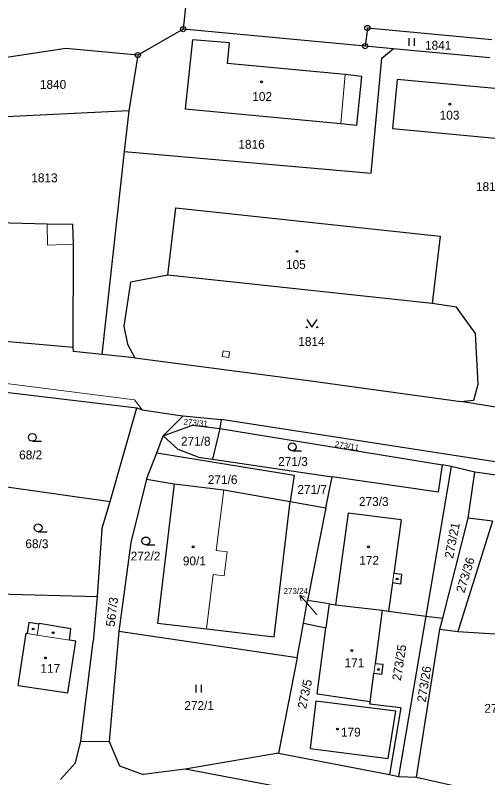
# Model space of a CAD drawing. Extents: x -601131 to -597152, y -1058536 to -1055911.
# Drawn here: x -599381.2 to -599290.5, y -1057201.3 to -1057055.1 of the extents above; entities that cross this region are included whole.
import ezdxf
from ezdxf.enums import TextEntityAlignment as Align

# ---------------------------------------------------------------- set-up
doc = ezdxf.new("R2010")
doc.units = 0
doc.header["$LTSCALE"] = 0.68
for name, color, linetype, lineweight in [('1', 7, 'Continuous', 25), ('3', 7, 'Continuous', 25), ('4', 7, 'Continuous', 13), ('5', 7, 'Continuous', 25), ('7', 7, 'Continuous', 13), ('8', 7, 'Continuous', 25)]:
    doc.layers.add(name, color=color, linetype=linetype, lineweight=lineweight)
doc.layers.add('2', color=7, linetype='Continuous')

msp = doc.modelspace()

# ---------------------------------------------------------------- linework, layer by layer
at = {"layer": '1'}
for p, q in [((-599345.57, -1057026.31), (-599349.02, -1057057.72)), ((-599349.02, -1057057.72), (-599357.72, -1057062.7)), ((-599314.09, -1057060.98), (-599349.02, -1057057.72)), ((-599313.65, -1057057.51), (-599314.09, -1057060.98)), ((-599289.75, -1057059.74), (-599313.65, -1057057.51)), ((-599347.24, -1057059.74), (-599348.63, -1057073.02)), ((-599340.09, -1057060.34), (-599347.24, -1057059.74)), ((-599340.49, -1057064.3), (-599340.09, -1057060.34)), ((-599308.72, -1057061.49), (-599314.09, -1057060.98)), ((-599371.54, -1057061.4), (-599383.28, -1057063.21)), ((-599357.72, -1057062.7), (-599371.54, -1057061.4)), ((-599310.9, -1057063.29), (-599308.72, -1057061.49)), ((-599290.14, -1057063.22), (-599308.72, -1057061.49)), ((-599357.72, -1057062.7), (-599359.44, -1057073.38)), ((-599312.94, -1057085.36), (-599310.9, -1057063.29)), ((-599317.89, -1057066.41), (-599340.49, -1057064.3)), ((-599314.7, -1057066.78), (-599317.89, -1057066.41)), ((-599315.69, -1057076.12), (-599314.7, -1057066.78)), ((-599307.96, -1057067.36), (-599308.83, -1057076.76)), ((-599285.62, -1057069.45), (-599307.96, -1057067.36)), ((-599359.44, -1057073.38), (-599384.42, -1057074.6)), ((-599359.44, -1057073.38), (-599360.32, -1057081.18)), ((-599348.63, -1057073.02), (-599318.77, -1057075.79)), ((-599318.77, -1057075.79), (-599315.69, -1057076.12)), ((-599308.83, -1057076.76), (-599286.54, -1057078.9)), ((-599360.32, -1057081.18), (-599364.64, -1057120.14)), ((-599360.32, -1057081.18), (-599312.94, -1057085.36)), ((-599351.94, -1057104.91), (-599350.44, -1057091.99)), ((-599350.44, -1057091.99), (-599299.69, -1057097.43)), ((-599375.11, -1057095.12), (-599389.23, -1057094.77)), ((-599370.16, -1057095.2), (-599375.11, -1057095.12)), ((-599370.08, -1057098.98), (-599370.16, -1057095.2)), ((-599299.69, -1057097.43), (-599301.18, -1057110.36)), ((-599370.11, -1057118.82), (-599370.08, -1057098.98)), ((-599351.94, -1057104.91), (-599359.13, -1057106.27)), ((-599301.18, -1057110.36), (-599351.94, -1057104.91)), ((-599359.13, -1057106.27), (-599360.39, -1057114.73)), ((-599296.51, -1057111.08), (-599301.18, -1057110.36)), ((-599292.92, -1057116.08), (-599296.51, -1057111.08)), ((-599360.39, -1057114.73), (-599359.72, -1057118.15)), ((-599292.39, -1057125.84), (-599292.92, -1057116.08)), ((-599370.11, -1057118.82), (-599392.44, -1057116.83)), ((-599359.72, -1057118.15), (-599358.28, -1057120.79)), ((-599370.06, -1057119.59), (-599370.11, -1057118.82)), ((-599364.64, -1057120.14), (-599370.06, -1057119.59)), ((-599358.28, -1057120.79), (-599364.64, -1057120.14)), ((-599358.28, -1057120.79), (-599324.53, -1057125.19)), ((-599324.53, -1057125.19), (-599295.71, -1057129.16)), ((-599392.5, -1057126.24), (-599357.9, -1057130.4)), ((-599293.18, -1057128.9), (-599292.39, -1057125.84)), ((-599295.71, -1057129.16), (-599293.18, -1057128.9)), ((-599293.72, -1057129.47), (-599295.71, -1057129.16)), ((-599283.88, -1057131.11), (-599293.72, -1057129.47)), ((-599363.04, -1057148.31), (-599357.9, -1057130.4)), ((-599357.9, -1057130.4), (-599356.88, -1057130.74)), ((-599356.88, -1057130.74), (-599350.04, -1057131.76)), ((-599352.87, -1057135.75), (-599348.99, -1057131.89)), ((-599350.04, -1057131.76), (-599348.99, -1057131.89)), ((-599348.99, -1057131.89), (-599341.7, -1057132.63)), ((-599341.7, -1057132.63), (-599341.95, -1057134.36)), ((-599279.34, -1057142.28), (-599341.7, -1057132.63)), ((-599352.87, -1057135.75), (-599347.22, -1057133.71)), ((-599347.22, -1057133.71), (-599341.95, -1057134.36)), ((-599354.07, -1057138.97), (-599352.87, -1057135.75)), ((-599352.87, -1057135.75), (-599349.95, -1057138.35)), ((-599341.95, -1057134.36), (-599343.35, -1057140.21)), ((-599341.95, -1057134.36), (-599299.2, -1057141.28)), ((-599346.16, -1057139.82), (-599349.95, -1057138.35)), ((-599356.03, -1057144.08), (-599354.07, -1057138.97)), ((-599354.07, -1057138.97), (-599327.73, -1057143.26)), ((-599346.16, -1057139.82), (-599343.35, -1057140.21)), ((-599343.35, -1057140.21), (-599320.42, -1057143.61)), ((-599299.97, -1057146.53), (-599299.2, -1057141.28)), ((-599297.54, -1057141.64), (-599299.2, -1057141.28)), ((-599297.54, -1057141.64), (-599302.44, -1057170.31)), ((-599293, -1057142.72), (-599297.54, -1057141.64)), ((-599294.32, -1057151.54), (-599293, -1057142.72)), ((-599279.71, -1057144.58), (-599293, -1057142.72)), ((-599394.87, -1057143.82), (-599363.04, -1057148.31)), ((-599356.03, -1057144.08), (-599359.06, -1057156.23)), ((-599356.03, -1057144.08), (-599350.75, -1057144.95)), ((-599327.73, -1057143.26), (-599328.49, -1057148.34)), ((-599321.65, -1057149.53), (-599320.42, -1057143.61)), ((-599299.97, -1057146.53), (-599320.42, -1057143.61)), ((-599350.75, -1057144.95), (-599353.95, -1057171.65)), ((-599350.75, -1057144.95), (-599341.22, -1057146.13)), ((-599341.22, -1057146.13), (-599328.49, -1057148.34)), ((-599364.62, -1057153.64), (-599363.04, -1057148.31)), ((-599331.57, -1057174.28), (-599328.49, -1057148.34)), ((-599328.49, -1057148.34), (-599321.65, -1057149.53)), ((-599321.65, -1057149.53), (-599325.14, -1057167.36)), ((-599317.36, -1057150.56), (-599319.79, -1057168.13)), ((-599307.19, -1057151.88), (-599317.36, -1057150.56)), ((-599299.15, -1057170.73), (-599294.32, -1057151.54)), ((-599289.64, -1057152.13), (-599294.32, -1057151.54)), ((-599307.19, -1057151.88), (-599308.59, -1057162.13)), ((-599289.64, -1057152.13), (-599296.29, -1057173.26)), ((-599364.62, -1057153.64), (-599365.52, -1057166.56)), ((-599359.06, -1057156.23), (-599361.33, -1057173.26)), ((-599307.08, -1057162.33), (-599308.59, -1057162.13)), ((-599307.08, -1057162.33), (-599307.32, -1057164.17)), ((-599308.84, -1057163.96), (-599309.58, -1057169.4)), ((-599307.32, -1057164.17), (-599308.84, -1057163.96)), ((-599395.07, -1057165.74), (-599365.52, -1057166.56)), ((-599365.52, -1057166.56), (-599366.32, -1057175.2)), ((-599325.93, -1057171.7), (-599325.14, -1057167.36)), ((-599320.98, -1057167.97), (-599325.14, -1057167.36)), ((-599320.98, -1057167.97), (-599321.6, -1057172.59)), ((-599320.98, -1057167.97), (-599319.79, -1057168.13)), ((-599319.79, -1057168.13), (-599310.82, -1057169.21)), ((-599310.82, -1057169.21), (-599312.17, -1057179.49)), ((-599310.82, -1057169.21), (-599309.58, -1057169.4)), ((-599309.58, -1057169.4), (-599302.44, -1057170.31)), ((-599302.44, -1057170.31), (-599307.7, -1057201.07)), ((-599302.44, -1057170.31), (-599299.15, -1057170.73)), ((-599299.74, -1057172.84), (-599299.15, -1057170.73)), ((-599378.65, -1057171.56), (-599378.97, -1057173.63)), ((-599376.7, -1057171.89), (-599378.65, -1057171.56)), ((-599376.68, -1057171.76), (-599376.7, -1057171.89)), ((-599370.58, -1057172.77), (-599376.68, -1057171.76)), ((-599353.95, -1057171.65), (-599344.52, -1057172.78)), ((-599327.12, -1057178.31), (-599325.93, -1057171.7)), ((-599325.93, -1057171.7), (-599324.38, -1057172.02)), ((-599324.38, -1057172.02), (-599321.89, -1057172.53)), ((-599380.68, -1057183.61), (-599379.12, -1057173.61)), ((-599379.12, -1057173.61), (-599378.97, -1057173.63)), ((-599370.86, -1057174.97), (-599370.58, -1057172.77)), ((-599361.33, -1057173.26), (-599363.21, -1057194.4)), ((-599327.12, -1057178.31), (-599361.33, -1057173.26)), ((-599344.52, -1057172.78), (-599331.57, -1057174.28)), ((-599323.31, -1057185.31), (-599321.6, -1057172.59)), ((-599321.89, -1057172.53), (-599321.6, -1057172.59)), ((-599304.24, -1057201.25), (-599299.74, -1057172.84)), ((-599299.74, -1057172.84), (-599296.29, -1057173.26)), ((-599296.29, -1057173.26), (-599274.91, -1057174.6)), ((-599371.18, -1057185.04), (-599369.62, -1057175.13)), ((-599369.62, -1057175.13), (-599370.86, -1057174.97)), ((-599368.68, -1057194.29), (-599366.32, -1057175.2)), ((-599327.12, -1057178.31), (-599330.73, -1057196.61)), ((-599310.63, -1057179.64), (-599312.17, -1057179.49)), ((-599310.88, -1057181.51), (-599310.63, -1057179.64)), ((-599313.12, -1057186.74), (-599312.41, -1057181.33)), ((-599310.88, -1057181.51), (-599312.41, -1057181.33)), ((-599380.68, -1057183.61), (-599371.18, -1057185.04)), ((-599313.12, -1057186.74), (-599323.31, -1057185.31)), ((-599323.53, -1057186.67), (-599324.62, -1057195.73)), ((-599308.18, -1057188.54), (-599323.53, -1057186.67)), ((-599313.12, -1057186.74), (-599313.26, -1057187.25)), ((-599307.23, -1057187.89), (-599313.26, -1057187.25)), ((-599307.23, -1057187.89), (-599309.37, -1057200.73)), ((-599309.65, -1057197.67), (-599308.18, -1057188.54)), ((-599369.66, -1057198.5), (-599368.68, -1057194.29)), ((-599368.68, -1057194.29), (-599363.21, -1057194.4)), ((-599363.21, -1057194.4), (-599361.26, -1057199.05)), ((-599324.62, -1057195.73), (-599309.65, -1057197.67)), ((-599330.73, -1057196.61), (-599348.62, -1057199.67)), ((-599330.73, -1057196.61), (-599309.37, -1057200.73)), ((-599372.53, -1057201.69), (-599369.66, -1057198.5)), ((-599361.26, -1057199.05), (-599356.7, -1057200.73)), ((-599348.62, -1057199.67), (-599356.7, -1057200.73)), ((-599331.73, -1057202.88), (-599348.62, -1057199.67)), ((-599309.37, -1057200.73), (-599307.7, -1057201.07)), ((-599307.7, -1057201.07), (-599304.24, -1057201.25)), ((-599304.24, -1057201.25), (-599280.22, -1057206.58))]:
    msp.add_line(p, q, dxfattribs=at)
at = {"layer": '3'}
for p, q in [((-599305.621, -1057060.92), (-599305.621, -1057059.42)), ((-599304.62, -1057060.92), (-599304.62, -1057059.42)), ((-599377.963, -1057136.79), (-599376.213, -1057136.79)), ((-599328.053, -1057138.61), (-599326.303, -1057138.61)), ((-599376.853, -1057154.15), (-599375.103, -1057154.15)), ((-599356.173, -1057156.65), (-599354.423, -1057156.65)), ((-599346.491, -1057184.99), (-599346.491, -1057183.49)), ((-599345.49, -1057184.99), (-599345.49, -1057183.49))]:
    msp.add_line(p, q, dxfattribs=at)
msp.add_lwpolyline([(-599325.28, -1057113.419), (-599324.28, -1057114.92), (-599323.28, -1057113.419)], dxfattribs=at)
for centre, radius in [((-599325.28, -1057114.9195), 0.1), ((-599323.28, -1057114.9195), 0.1), ((-599377.9629, -1057136.0398), 0.75), ((-599328.0529, -1057137.8598), 0.75), ((-599376.8529, -1057153.3998), 0.75), ((-599356.1729, -1057155.8998), 0.75)]:
    msp.add_circle(centre, radius, dxfattribs=at)
at = {"layer": '4'}
for p, q in [((-599317.89, -1057066.41), (-599318.77, -1057075.79)), ((-599375.06, -1057099.18), (-599375.11, -1057095.12)), ((-599375.06, -1057099.18), (-599370.08, -1057098.98)), ((-599341.51, -1057120.52), (-599341.36, -1057119.44)), ((-599341.36, -1057119.44), (-599340.11, -1057119.62)), ((-599340.11, -1057119.62), (-599340.25, -1057120.69)), ((-599340.25, -1057120.69), (-599341.51, -1057120.52)), ((-599391.34, -1057124.68), (-599358.33, -1057128.81)), ((-599358.33, -1057128.81), (-599356.88, -1057130.74)), ((-599342.65, -1057157.72), (-599341.22, -1057146.13)), ((-599340.58, -1057157.98), (-599342.65, -1057157.72)), ((-599343.24, -1057162.32), (-599344.52, -1057172.78)), ((-599308.59, -1057162.13), (-599308.84, -1057163.96)), ((-599377.02, -1057173.95), (-599376.7, -1057171.89)), ((-599378.97, -1057173.63), (-599377.02, -1057173.95)), ((-599370.86, -1057174.97), (-599377.02, -1057173.95)), ((-599312.17, -1057179.49), (-599312.41, -1057181.33))]:
    msp.add_line(p, q, dxfattribs=at)
msp.add_lwpolyline([(-599340.58, -1057157.98), (-599341.13, -1057162.58), (-599343.24, -1057162.32)], dxfattribs=at)
at = {"layer": '5'}
for centre in [(-599333.9668, -1057067.8392), (-599297.8068, -1057072.1092), (-599327.1568, -1057100.3592), (-599347.0768, -1057157.0292), (-599313.4468, -1057157.0492), (-599307.9268, -1057163.2092), (-599377.8268, -1057172.7992), (-599373.9568, -1057173.5092), (-599375.4268, -1057178.3492), (-599316.6568, -1057176.9392), (-599311.5368, -1057180.5792), (-599319.4068, -1057191.9892)]:
    msp.add_circle(centre, 0.175, dxfattribs=at)
at = {"layer": '7'}
msp.add_line((-599326.609, -1057166.295), (-599326.33, -1057167.379), dxfattribs=at)
msp.add_lwpolyline([(-599323.35, -1057170.06), (-599324.64, -1057168.56), (-599326.609, -1057166.295), (-599325.574, -1057166.722)], dxfattribs=at)
at = {"layer": '8'}
for centre, radius in [((-599349.02, -1057057.7199), 0.5), ((-599349.02, -1057057.7199), 0.0303), ((-599313.65, -1057057.5099), 0.5), ((-599313.65, -1057057.5099), 0.0303), ((-599314.09, -1057060.9799), 0.5), ((-599314.09, -1057060.9799), 0.0303), ((-599357.72, -1057062.6999), 0.5), ((-599357.72, -1057062.6999), 0.0303)]:
    msp.add_circle(centre, radius, dxfattribs=at)

# ---------------------------------------------------------------- texts
at = {"layer": '2'}
for s, p in [('1841', (-599300.06, -1057061.662)), ('1840', (-599373.99, -1057069.172)), ('102', (-599333.849, -1057071.492)), ('103', (-599297.879, -1057075.062)), ('1816', (-599335.88, -1057080.662)), ('1813', (-599375.64, -1057087.092)), ('1815', (-599290.28, -1057088.782)), ('105', (-599327.369, -1057103.722)), ('1814', (-599324.38, -1057118.492))]:
    msp.add_text(s, height=1.7, dxfattribs=at).set_placement(p, align=Align.CENTER)
for s, height, rotation, p in [('273/31', 1.14, 355, (-599348.974, -1057133.593)), ('273/11', 1.14, 351, (-599319.954, -1057137.861)), ('273/21', 1.7, 79, (-599297.202, -1057159.371)), ('273/36', 1.7, 73, (-599295.043, -1057166.004)), ('567/3', 1.7, 83, (-599362.188, -1057172.441)), ('273/25', 1.7, 81, (-599307.23, -1057182.806)), ('273/26', 1.7, 81, (-599302.45, -1057186.926)), ('273/5', 1.7, 78, (-599325.414, -1057188.228))]:
    msp.add_text(s, height=height, rotation=rotation, dxfattribs=at).set_placement(p)
for s, p in [('271/8', (-599349.44, -1057137.635)), ('68/2', (-599380.5, -1057140.245)), ('271/3', (-599330.77, -1057141.515)), ('271/6', (-599344.28, -1057145.005)), ('271/7', (-599327.09, -1057146.875)), ('273/3', (-599315.27, -1057149.205)), ('68/3', (-599379.3, -1057157.295)), ('272/2', (-599359.08, -1057159.655)), ('90/1', (-599349.07, -1057160.584)), ('172', (-599315.21, -1057160.475)), ('117', (-599376.41, -1057181.205)), ('171', (-599318.03, -1057180.125)), ('272/1', (-599348.79, -1057188.334)), ('273/8', (-599291.18, -1057188.875)), ('179', (-599318.72, -1057193.435))]:
    msp.add_text(s, height=1.7, dxfattribs=at).set_placement(p)
msp.add_text('273/24', height=1.14, dxfattribs=at).set_placement((-599325.06, -1057166.095), align=Align.RIGHT)

doc.saveas('drawing.dxf')
